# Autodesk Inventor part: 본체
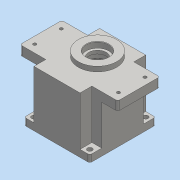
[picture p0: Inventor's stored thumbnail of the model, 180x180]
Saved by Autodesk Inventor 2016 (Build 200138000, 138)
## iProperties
Created: 2020-08
Part Number: 본체
Material: 일반
Document SubType Name: Modeling
Designer: User
Density: 1 g/cm^3
Appearance: 기본값
Mass: 324.574 g
Surface Area: 793.93 cm^2
Volume: 324.574 cm^3
Author: User
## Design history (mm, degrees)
sketch "스케치1"
  geometry: L1 (-70, 30)-(70, 30); L2 (70, 30)-(70, -30); L3 (70, -30)-(-70, -30); L4 (-70, -30)-(-70, 30); L5 (-70, 30)-(70, -30); L6 (70, 30)-(-70, -30); L7 (-33, 47)-(33, 47); L8 (33, 47)-(33, -47); L9 (33, -47)-(-33, -47); L10 (-33, -47)-(-33, 47); L11 (-33, 47)-(33, -47); L12 (33, 47)-(-33, -47); 1 further point
  constraints: 24 end point, 4 midpoint, 4 parallel, 2 horizontal, 2 perpendicular
  dimensions: "d0" = 140 distance of L2.end L3.end; "d1" = 60 distance of L1.end L2.end; "d2" = 66 distance of L8.end L9.end; "d3" = 94 distance of L7.end L8.end
extrude "돌출1" new body sketch "스케치1" distance "d4" = 80; taper "d5" = 0 deg
sketch "스케치2"
  geometry: C1 r 27.5 at (0, 11); 1 further point
  constraints: 1 centre point, 1 vertical alignment
  dimensions: "d6" = 55 diameter of C1; "d7" = 11 distance of point (0, 0) C1.centre
extrude "돌출2" join sketch "스케치2" distance "d8" = 7; taper "d9" = 0 deg
hole "구멍1" diameter "d12" = 32; stored, may be unused: countersink angle "d16" = 90 deg, drill point angle "d18" = 0 deg; dims "d13" = 6, "d14" = 4, "d15" = 2, "d17" = 8.3, "d40" = 10, "d41" = 10
hole "구멍2" diameter "d21" = 25; stored, may be unused: countersink angle "d25" = 90 deg, drill point angle "d27" = 0 deg; dims "d22" = 6, "d23" = 4, "d24" = 2, "d26" = 13, "d38" = 10, "d39" = 10
sketch "스케치4"
  geometry: L1 (47, 47)-(-47, 47); L2 (-47, 47)-(-47, -47); L3 (-47, -47)-(47, -47); L4 (47, -47)-(47, 47); L5 (47, 47)-(-47, -47); L6 (-47, 47)-(47, -47); 1 further point
  constraints: 12 end point, 2 midpoint, 2 parallel, 1 horizontal, 1 perpendicular
  dimensions: "d28" = 94 distance of L3.end L2.end; "d29" = 94 distance of L2.end L1.end
extrude "돌출3" join sketch "스케치4" distance "d30" = 10; taper "d31" = 0 deg
sketch "스케치5"
  geometry: C1 r 43 at (0, 0); 1 further point
  constraints: 1 centre point, 1 coincident
  dimensions: "d32" = 86 diameter of C1
extrude "돌출4" cut sketch "스케치5" distance "d33" = 9; taper "d34" = 0 deg
sketch "스케치6"
  geometry: C1 r 40 at (0, 0); 1 further point
  constraints: 1 centre point, 1 coincident
  dimensions: "d35" = 80 diameter of C1
extrude "돌출5" cut sketch "스케치6" distance "d36" = 71; taper "d37" = 0 deg
sketch "스케치7"
  geometry: C1 r 21 at (0, 11); C2 r 15 at (0, -20); 1 further point
  constraints: 2 centre point, 2 vertical alignment
  dimensions: "d42" = 42 diameter of C1; "d44" = 11 distance of point (0, 0) C1.centre; "d45" = 30 diameter of C2; "d46" = 20 distance of point (0, 0) C2.centre
extrude "돌출6" join sketch "스케치7" distance "d47" = 7; taper "d48" = 0 deg
hole "구멍3" diameter "d51" = 35; stored, may be unused: countersink angle "d55" = 90 deg, drill point angle "d57" = 0 deg; dims "d49" = 10, "d50" = 10, "d52" = 6, "d53" = 4, "d54" = 2, "d56" = 10
hole "구멍4" diameter "d60" = 22; stored, may be unused: countersink angle "d64" = 90 deg, drill point angle "d66" = 0 deg; dims "d61" = 6, "d62" = 4, "d63" = 2, "d65" = 7, "d145" = 10, "d146" = 10
hole "구멍5" diameter "d69" = 19; stored, may be unused: countersink angle "d73" = 90 deg, drill point angle "d75" = 0 deg; dims "d70" = 6, "d71" = 4, "d72" = 2, "d74" = 10, "d143" = 10, "d144" = 10
sketch "스케치9"
  geometry: L1 (-47, 47)-(47, 47); L2 (47, 47)-(47, -47); L3 (47, -47)-(-47, -47); L4 (-47, -47)-(-47, 47); L5 (-47, 47)-(47, -47); L6 (47, 47)-(-47, -47); L7 (-100, 100)-(100, 100); L8 (100, 100)-(100, -100); L9 (100, -100)-(-100, -100); L10 (-100, -100)-(-100, 100); L11 (-100, 100)-(100, -100); L12 (100, 100)-(-100, -100); 1 further point
  constraints: 24 end point, 4 midpoint, 4 parallel, 2 horizontal, 2 perpendicular, 1 point on line
  dimensions: "d76" = 94 distance of L2.end L3.end; "d77" = 94 distance of L1.end L2.end; "d78" = 200 distance of L8.end L9.end
extrude "돌출7" cut sketch "스케치9" distance "d79" = 67; taper "d80" = 0 deg
sketch "스케치10"
  geometry: 2 further points
  dimensions: "d81" = 40 horizontal distance of point (0, 0) point (-40, 40); "d82" = 40 horizontal distance of point (0, 0) point (-40, 40)
hole "구멍6" sketch "스케치10" at (-40, 40) diameter "d83" = 7; stored, may be unused: countersink angle "d87" = 90 deg, drill point angle "d89" = 0 deg; dims "d84" = 6, "d85" = 4, "d86" = 2, "d88" = 10
sketch "스케치12"
  geometry: 2 further points
  dimensions: "d96" = 60 horizontal distance of point (0, 0) point (60, 19); "d97" = 19 vertical distance of point (0, 0) point (60, 19)
hole "구멍7" sketch "스케치12" at (60, 19) diameter "d98" = 4.5; stored, may be unused: countersink angle "d102" = 90 deg, drill point angle "d104" = 0 deg; dims "d99" = 6, "d100" = 10, "d101" = 5, "d103" = 13
sketch "스케치13"
  geometry: A1 r 21 centre (0, 11) between (8.978, -7.984) and (-8.978, -7.984) reference; A2 r 15 centre (0, -20) between (-8.978, -7.984) and (8.978, -7.984) reference; A3 r 40 centre (0, 0) between (39.279, 7.559) and (39.279, -7.559) reference; A4 r 4 centre (36, 0) between (36.19, 3.995) and (36.19, -3.995); A5 r 36 centre (0, 0) between (36, 0) and (35.772, 4.045); A6 r 3 centre (36.333, 6.992) between (35.772, 4.045) and (39.279, 7.559); A7 r 3 centre (36.333, -6.992) between (39.279, -7.559) and (35.772, -4.045); 1 further point
  constraints: 13 point on circle, 4 centre point, 4 tangent, 1 coincident, 1 horizontal alignment
  dimensions: "d111" = 8 diameter of A4; "d112" = 72 diameter of A5; "d113" = 6 diameter of A6; "d114" = 6 diameter of A7
extrude "돌출8" join sketch "스케치13" distance "d115" = 62; taper "d116" = 0 deg
hole "구멍8" diameter "d119" = 3.242; stored, may be unused: countersink angle "d123" = 90 deg, drill point angle "d125" = 118 deg; dims "d117" = 10, "d118" = 10, "d120" = 7, "d121" = 10, "d122" = 5, "d124" = 9
chamfer "모따기1" distance "d126" = 0.8; stored, may be unused: second distance "d127" = 2, angle "d128" = 30 deg
chamfer "모따기2" distance "d129" = 1; stored, may be unused: second distance "d130" = 2, angle "d131" = 30 deg
chamfer "모따기3" distance "d132" = 1; stored, may be unused: second distance "d133" = 2, angle "d134" = 30 deg
fillet "모깎기1" dims "d135" = 3
fillet "모깎기2" dims "d136" = 3
fillet "모깎기3" dims "d137" = 3
sketch "스케치14"
  geometry: L1 (-11, 80)-(77, 80) reference; L2 (0, 0)-(66, 0) reference; 3 further points
  constraints: 1 midpoint, 1 vertical alignment, 1 other
  dimensions: "d138" = 40 distance from line of point (33, 40) L1
feature "엠보싱1" sketch "스케치14" dims "d0" = 140, "d1" = 60, "d23" = 4, "d139" = 0.5, "d140" = 0
node "솔리드1"
pattern_linear "직사각형 패턴1" dims "d92" = 80
pattern_linear "직사각형 패턴2" dims "d107" = 120, "d110" = 38
mirror "대칭1"
node "투영된 루프1"
